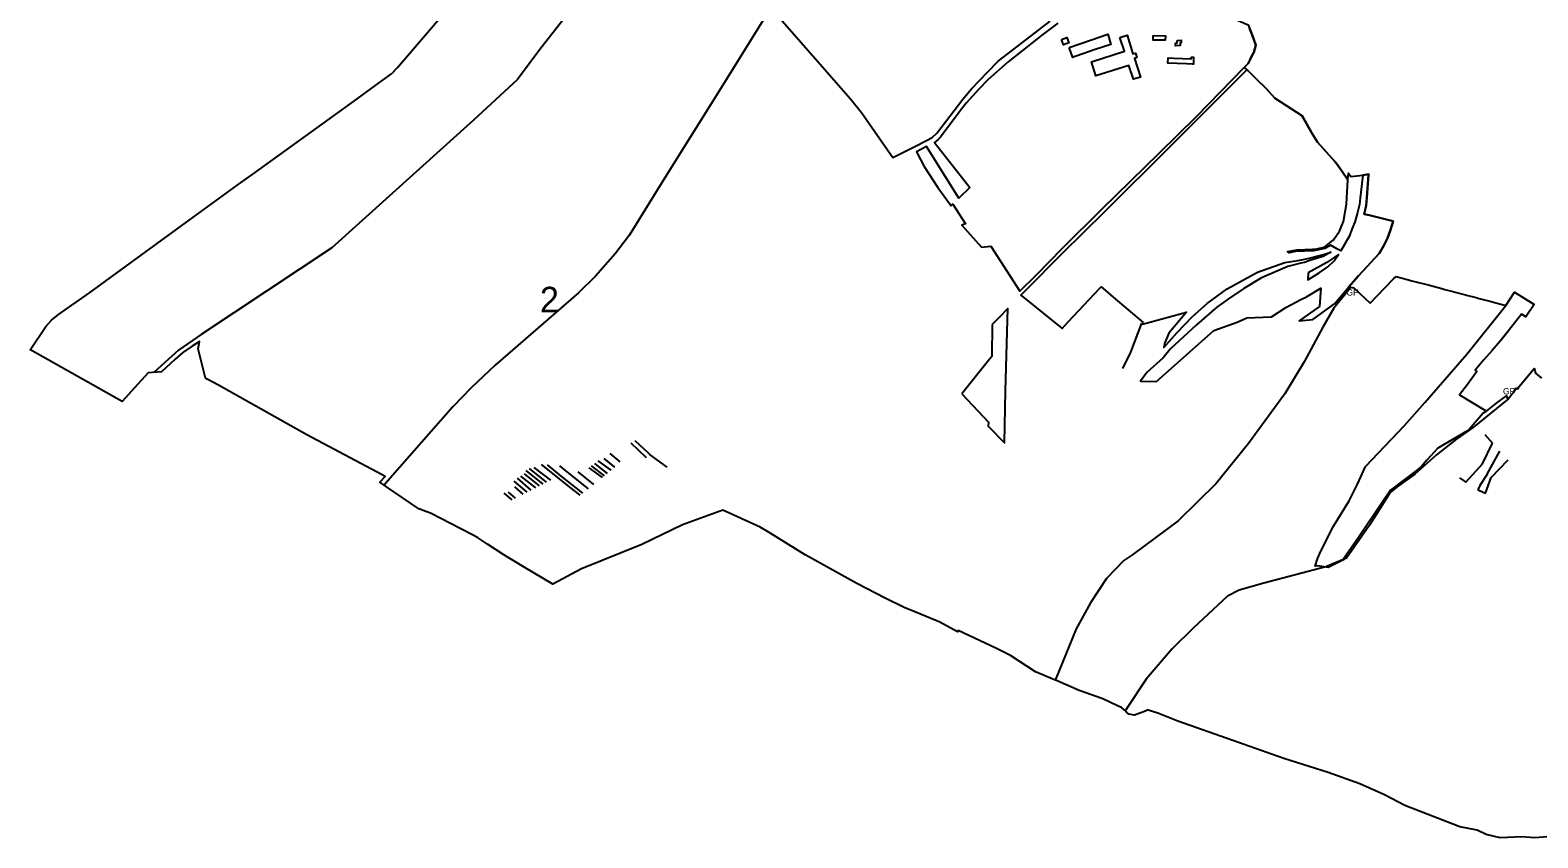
# Model space of a CAD drawing. Extents: x -584576 to -579722, y -1113169 to -1110375.
# Drawn here: x -584240 to -581887, y -1113088 to -1111827 of the extents above; entities that cross this region are included whole.
import ezdxf

# ---------------------------------------------------------------- set-up
doc = ezdxf.new("R2010")
doc.units = 0
for name, color, linetype in [('CESTY', 7, 'Continuous'), ('GRA_ZV', 7, 'Continuous'), ('LES_ZV', 7, 'Continuous'), ('Level 255', 7, 'Continuous'), ('OVNE_PRE', 7, 'Continuous'), ('OVNE_SET', 7, 'Continuous'), ('OVNI_PRE', 7, 'Continuous'), ('OVNI_SET', 7, 'Continuous'), ('VODA', 7, 'Continuous')]:
    doc.layers.add(name, color=color, linetype=linetype)

msp = doc.modelspace()

# ---------------------------------------------------------------- linework, layer by layer
at = {"layer": 'CESTY'}
for points in [[(-583086.3, -1111796.1), (-583161.2, -1111917), (-583248.8, -1112057.5), (-583304.8, -1112147.4), (-583326.6, -1112176.1), (-583357.4, -1112211.2), (-583383.9, -1112237.1), (-583513.8, -1112350.2), (-583551.3, -1112385.3), (-583579.8, -1112414.8), (-583681.5, -1112530.8), (-583687.3, -1112537.3)], [(-582178.9, -1112229.2), (-582204.8, -1112261), (-582222.1, -1112290.5), (-582251.3, -1112344.5), (-582281.6, -1112394.7), (-582338.2, -1112472.3), (-582388.4, -1112534.7), (-582447.9, -1112593.1), (-582518.9, -1112645.6), (-582532.5, -1112654.8), (-582559.9, -1112683.2), (-582584.6, -1112721.3), (-582607.2, -1112761.6), (-582639.3, -1112841)]]:
    msp.add_lwpolyline(points, dxfattribs=at)
at = {"layer": 'GRA_ZV'}
for p, q in [((-582178.6, -1112055.2), (-582178.6, -1112055.2)), ((-582112.5, -1112124.9), (-582149.6, -1112115.9)), ((-582112.5, -1112124.9), (-582112.5, -1112124.9)), ((-582210.1, -1112162.7), (-582210.1, -1112162.7)), ((-582738.4, -1112286.7), (-582738.8, -1112336.2))]:
    msp.add_line(p, q, dxfattribs=at)
for points in [[(-583076.7, -1111799.7), (-582959.4, -1111934.2), (-582942.1, -1111955.5), (-582893.2, -1112025.7), (-582874.5, -1112016.1), (-582857.8, -1112007.8), (-582840.6, -1111998.9), (-582832, -1111994.4), (-582824.5, -1111987.5), (-582784, -1111934.4), (-582770.3, -1111918.7), (-582745.7, -1111892.2), (-582728.7, -1111875.4), (-582677.4, -1111835.6), (-582647.7, -1111813)], [(-582635.5, -1111815.8), (-582660.5, -1111834.8), (-582668.5, -1111841.1), (-582713.4, -1111876.1), (-582745, -1111904.2), (-582758.9, -1111919.1), (-582778.8, -1111941.1), (-582786.6, -1111950.8), (-582818.7, -1111994.1), (-582822.2, -1111997.6), (-582828.1, -1112002.1), (-582772.9, -1112072.3), (-582790.2, -1112089.3), (-582840.8, -1112008.7), (-582856.3, -1112016.8), (-582855.2, -1112018.8), (-582844.2, -1112039.5), (-582822.9, -1112072.6), (-582803.4, -1112099.8), (-582802.6, -1112101), (-582799.8, -1112098.8), (-582779.6, -1112129.1), (-582785.5, -1112131.4), (-582755, -1112165.9), (-582740.2, -1112164.1), (-582695, -1112234.3), (-582668.7, -1112208.3), (-582629.1, -1112167.9), (-582566.3, -1112106.1), (-582477.3, -1112018.7), (-582419.3, -1111961.5), (-582344.7, -1111885.2), (-582338.8, -1111878.9), (-582335.5, -1111872.5), (-582332.3, -1111865.8), (-582330, -1111861.6), (-582326.9, -1111850.2), (-582332.6, -1111834.1), (-582336.5, -1111824)], [(-582629.8, -1111841.7), (-582621.6, -1111838.5), (-582618.5, -1111846.8), (-582626.8, -1111849.9), (-582629.8, -1111841.7)], [(-582617.8, -1111853.9), (-582583.3, -1111842.1), (-582557.7, -1111833.3), (-582557.2, -1111834.9), (-582553.9, -1111845.8), (-582552.9, -1111849), (-582577.3, -1111857.3), (-582606.9, -1111867.4), (-582609.2, -1111868.2), (-582612.5, -1111869.3), (-582614.8, -1111862.7), (-582617.8, -1111853.9)], [(-582538.7, -1111838.3), (-582527.7, -1111834.8), (-582518.4, -1111864), (-582514.5, -1111862.8), (-582514, -1111864.5), (-582512.3, -1111869.7), (-582516.1, -1111870.9), (-582506.8, -1111900.1), (-582517.8, -1111903.6), (-582524.7, -1111881.9), (-582576.3, -1111898.3), (-582583.3, -1111876.2), (-582531.8, -1111859.8), (-582538.7, -1111838.3)], [(-582486.8, -1111835.2), (-582467.7, -1111835.7), (-582468.1, -1111842.5), (-582486.8, -1111842.3), (-582486.8, -1111835.2)], [(-582449.6, -1111842.8), (-582443.2, -1111842.6), (-582443, -1111846.7), (-582445, -1111846.7), (-582444.9, -1111850.8), (-582452.2, -1111851.1), (-582452.3, -1111847), (-582449.5, -1111846.9), (-582449.6, -1111842.8)], [(-582427.4, -1111868.9), (-582423.8, -1111869), (-582424.2, -1111879.9), (-582426.3, -1111879.9), (-582434.8, -1111879.5), (-582464, -1111878.2), (-582463.7, -1111870.1), (-582454.8, -1111870.5), (-582427.5, -1111871.6), (-582427.4, -1111868.9)], [(-582340.8, -1111888.6), (-582461, -1112008.9), (-582562.8, -1112110.7), (-582628.4, -1112175.2), (-582686.5, -1112233.8), (-582693.3, -1112240.6), (-582674.9, -1112255.6), (-582629, -1112292.5), (-582619.4, -1112282.1), (-582570, -1112229.5), (-582568.2, -1112227.4), (-582557.5, -1112236.5), (-582549.1, -1112243.6), (-582502.6, -1112283.3)], [(-582324.6, -1111904.3), (-582339.1, -1111890.1), (-582340.8, -1111888.6)], [(-582199, -1112037), (-582203.4, -1112031.7), (-582230.5, -1112001.7), (-582240, -1111986.6), (-582254.3, -1111960.7), (-582297.2, -1111933), (-582310.9, -1111917.4), (-582324.6, -1111904.3)], [(-582150.6, -1112051.8), (-582159.9, -1112053.5), (-582163.8, -1112088.7), (-582164.9, -1112099.3), (-582168.2, -1112111.6), (-582172.2, -1112126.5), (-582176.8, -1112137.8), (-582180.7, -1112148.2), (-582193.8, -1112171.5), (-582198, -1112169.2), (-582200.1, -1112168.1), (-582210.1, -1112162.7), (-582218.9, -1112167.7), (-582236.6, -1112171.5), (-582264.7, -1112172.6), (-582274.6, -1112174.7), (-582277.1, -1112172.5), (-582262.1, -1112169.9), (-582238.4, -1112168.6), (-582231.7, -1112168.2), (-582220.4, -1112165.8), (-582219.7, -1112165.6), (-582205.6, -1112154.5), (-582196.1, -1112140.8), (-582190.1, -1112125.5), (-582185.4, -1112098.5), (-582183.2, -1112060.4), (-582192, -1112047.3), (-582194.4, -1112043.8), (-582199, -1112037)], [(-582149.6, -1112115.9), (-582157.4, -1112114.1), (-582154.4, -1112100.5), (-582153.5, -1112088.1), (-582150.7, -1112052.8), (-582150.6, -1112051.8)], [(-582195.2, -1112244), (-582181.4, -1112227.8), (-582166.3, -1112210.6), (-582134.3, -1112175.7), (-582127.5, -1112164.4), (-582121.4, -1112151.7), (-582117.3, -1112140.2), (-582113.3, -1112128.7), (-582112.5, -1112124.9)], [(-582449.4, -1112299.1), (-582426, -1112274.3), (-582402.9, -1112253.7), (-582371.6, -1112230.7), (-582323.9, -1112205), (-582281.5, -1112189.7), (-582261.2, -1112186.4), (-582252.6, -1112185), (-582243.5, -1112183), (-582229.2, -1112179.4), (-582221.3, -1112177.1), (-582209.4, -1112173.7), (-582221.6, -1112180.1), (-582229.1, -1112182.4), (-582243.8, -1112187.2), (-582250.6, -1112189.5), (-582256.5, -1112190.5)], [(-582245, -1112205.8), (-582245.7, -1112216.6), (-582234.4, -1112209.8), (-582228.1, -1112205.9), (-582214.3, -1112196.5), (-582204.4, -1112186.9), (-582197.6, -1112176.9), (-582216, -1112189.9), (-582245, -1112205.8)], [(-582256.5, -1112190.5), (-582276.8, -1112195.9), (-582318, -1112213.8), (-582345.4, -1112230.2), (-582369.6, -1112246.2), (-582387.7, -1112259.5), (-582419.1, -1112286.9), (-582460.3, -1112325.1), (-582471.3, -1112338.7), (-582496.8, -1112361.4), (-582506.8, -1112375), (-582481.5, -1112375.4), (-582392.4, -1112296), (-582355.8, -1112282.7), (-582340.7, -1112276.3), (-582302.2, -1112274.6)], [(-582302.2, -1112274.6), (-582279.8, -1112259.8), (-582256.3, -1112247.5), (-582247.8, -1112243.1), (-582225, -1112229.7), (-582227.5, -1112258.5), (-582259.1, -1112280.8), (-582238, -1112278.5), (-582203.7, -1112254), (-582195.2, -1112244)], [(-582205.4, -1112601.6), (-582180.8, -1112561.6), (-582167.9, -1112535.9), (-582155.8, -1112508.1), (-582094.5, -1112444.1), (-582062.8, -1112408.2), (-581997.2, -1112332.9), (-581936.5, -1112256.6), (-581922.9, -1112236.1), (-581892.3, -1112255.4), (-581905.4, -1112274.5), (-581912.3, -1112270.1), (-581929, -1112291.7), (-581945.3, -1112312.6), (-581958, -1112327), (-581971.3, -1112342.4), (-581984.5, -1112358), (-581981.6, -1112359.9)], [(-582785.6, -1112394.9), (-582743.9, -1112439.2), (-582744.4, -1112445.4), (-582718.7, -1112471.2), (-582717.2, -1112390.1), (-582713.5, -1112261.3), (-582727.8, -1112276), (-582738.4, -1112286.7)], [(-582502.6, -1112283.3), (-582503.5, -1112285.8), (-582434.7, -1112267), (-582462.6, -1112300.2), (-582469.1, -1112316.2), (-582470.1, -1112322.2), (-582449.4, -1112299.1)], [(-582738.8, -1112336.2), (-582744.1, -1112342.8), (-582785.6, -1112394.9)], [(-581981.6, -1112359.9), (-581996.6, -1112380.1), (-582009, -1112396.1)], [(-582009, -1112396.1), (-581966.8, -1112421.9), (-581971.9, -1112424.8), (-581974.9, -1112428.3)], [(-581974.9, -1112428.3), (-581994, -1112450.6), (-581997.5, -1112453.2), (-582027.7, -1112470.9), (-582042.6, -1112479.6), (-582059.6, -1112498.5)], [(-582059.6, -1112498.5), (-582068.4, -1112508.3), (-582078.3, -1112515.8), (-582116.5, -1112545), (-582166.6, -1112619.1), (-582189.4, -1112651.6), (-582188.8, -1112653.6), (-582213.9, -1112665.9)], [(-582213.9, -1112665.9), (-582226.7, -1112663.9), (-582231.6, -1112663.1), (-582234.2, -1112663.9), (-582230.7, -1112652.2), (-582225.9, -1112641.2), (-582205.4, -1112601.6)]]:
    msp.add_lwpolyline(points, dxfattribs=at)
at = {"layer": 'LES_ZV'}
for p, q in [((-581969.3, -1112458.4), (-581957.5, -1112471.8)), ((-583318.6, -1112501), (-583334.3, -1112488)), ((-583277.7, -1112494.7), (-583301.7, -1112471.7)), ((-581965.9, -1112520.1), (-581946, -1112484.3)), ((-583438.9, -1112535.7), (-583465.5, -1112514.2)), ((-583433.5, -1112532.9), (-583460.3, -1112511.2)), ((-583426.7, -1112529.5), (-583453.2, -1112509.5)), ((-583346.3, -1112525.3), (-583366.9, -1112510.2)), ((-583343.3, -1112522.9), (-583363.6, -1112507)), ((-583338.3, -1112518.9), (-583358.1, -1112503.5)), ((-583332.9, -1112514), (-583353, -1112499.1)), ((-583327.1, -1112509), (-583343.9, -1112495.6)), ((-583463.8, -1112548.3), (-583484, -1112530.9)), ((-583457.4, -1112545.1), (-583479.2, -1112526.2)), ((-583450.6, -1112541.6), (-583473.6, -1112523.3)), ((-583444.6, -1112538.6), (-583468.2, -1112519.7)), ((-583359.8, -1112536.4), (-583384.3, -1112516.4)), ((-583487.3, -1112560.2), (-583499.9, -1112549.7)), ((-583482.3, -1112557.7), (-583493.2, -1112548.1)), ((-583469.9, -1112551.4), (-583483, -1112539.7))]:
    msp.add_line(p, q, dxfattribs=at)
for points in [[(-582505.1, -1112284.4), (-582522.2, -1112329.5), (-582535, -1112355.4)], [(-583245.6, -1112509.4), (-583271.9, -1112490.1), (-583274.6, -1112487.5), (-583295.2, -1112468.2)], [(-582009, -1112526), (-581998.8, -1112532.8), (-581973.2, -1112504), (-581958.1, -1112472.8), (-581957.5, -1112471.8)], [(-583380.9, -1112552.9), (-583395.4, -1112541.8), (-583441.5, -1112505.2)], [(-583376.8, -1112549.6), (-583411.2, -1112522.7), (-583432, -1112505.8)], [(-583368.1, -1112542.8), (-583404.2, -1112514.4), (-583413, -1112507.1)], [(-581965.9, -1112520.1), (-581966.4, -1112521.1), (-581977.1, -1112537.9), (-581979.5, -1112543.6), (-581979.9, -1112544.6), (-581971.8, -1112548.2), (-581968.4, -1112549.9), (-581959.5, -1112525.4), (-581932.8, -1112497.6)]]:
    msp.add_lwpolyline(points, dxfattribs=at)
at = {"layer": 'Level 255'}
for p, q in [((-583676.8, -1112511.2), (-583676.8, -1112511.2)), ((-581960.9, -1112507.7), (-581960.9, -1112507.7))]:
    msp.add_line(p, q, dxfattribs=at)
at = {"layer": 'OVNE_PRE'}
for points in [[(-583891.8, -1112051.5), (-583740.7, -1111942.5), (-583688.5, -1111904.6), (-583675.7, -1111894.8), (-583666.2, -1111885.1), (-583600.7, -1111808.6), (-583566.2, -1111771.3), (-583537.4, -1111740.1), (-583451.5, -1111647.2), (-583441.4, -1111636.3), (-583367.8, -1111556.5), (-583325, -1111510.2), (-583316.9, -1111501.4), (-583239, -1111417.4), (-583191.9, -1111366.6), (-583170.1, -1111343.2)], [(-583966, -1112370.3), (-583977.1, -1112324.5), (-583975.1, -1112312.9), (-583986.8, -1112320.5), (-584001.1, -1112330.3), (-584013.8, -1112341.1), (-584034.7, -1112360.3), (-584055.6, -1112361.9), (-584076.8, -1112385.2), (-584095.8, -1112406.8), (-584236.3, -1112327.8), (-584239.5, -1112325.8), (-584214.8, -1112289.7), (-584206.1, -1112279.7), (-584195.4, -1112270.8), (-584147.1, -1112236.8), (-583985.5, -1112119.3), (-583911.2, -1112065.4), (-583891.8, -1112051.5)]]:
    msp.add_lwpolyline(points, dxfattribs=at)
at = {"layer": 'OVNE_SET'}
for p, q in [((-581971.3, -1112342.4), (-581971.3, -1112342.4)), ((-581958, -1112327), (-581958, -1112327)), ((-583963.2, -1112371.8), (-583966, -1112370.3))]:
    msp.add_line(p, q, dxfattribs=at)
for points in [[(-583024.4, -1112649), (-583029.8, -1112645.9), (-583086, -1112611.1), (-583100.2, -1112602.9), (-583158.5, -1112576.4), (-583221.3, -1112599.2), (-583284.8, -1112630.1), (-583379, -1112668.1), (-583423.8, -1112692.1), (-583468.6, -1112665.6), (-583500.3, -1112646.1), (-583525.9, -1112629.2), (-583541.5, -1112618.9), (-583550.4, -1112614.3), (-583614.8, -1112581.2), (-583621.8, -1112578.5), (-583633, -1112574.2), (-583634.4, -1112573.2), (-583681.8, -1112541.1), (-583694, -1112532.8), (-583685.6, -1112523.7), (-583690.4, -1112521.2), (-583807.7, -1112459), (-583945.8, -1112381.3), (-583963.2, -1112371.8)], [(-582094.2, -1113037.6), (-582125.9, -1113020.8), (-582164.5, -1113003.6), (-582213.8, -1112985.9), (-582283, -1112964.1), (-582362.5, -1112935.9), (-582448.2, -1112906), (-582479.6, -1112893.5), (-582496.5, -1112888.1), (-582497.8, -1112889.6), (-582515.8, -1112896.5), (-582525, -1112894.7), (-582528.3, -1112891.6), (-582530.7, -1112889.4), (-582532.5, -1112887.8), (-582536.3, -1112884.3), (-582542.5, -1112881.7), (-582565.5, -1112871.2), (-582602.3, -1112858), (-582636.8, -1112842.6), (-582643.7, -1112840.4), (-582670.4, -1112828.8), (-582709.8, -1112803.4), (-582732.3, -1112792.1), (-582791, -1112764.1), (-582792.1, -1112766.2), (-582819.7, -1112751.1), (-582856.3, -1112736.1), (-582875.3, -1112728.1), (-582905.4, -1112713.6), (-582949.4, -1112690.9), (-583024.4, -1112649)], [(-581859.1, -1113085.4), (-581865.3, -1113085.9), (-581866.1, -1113086), (-581867, -1113086.1), (-581878.3, -1113086.9), (-581892, -1113088.1), (-581910.8, -1113086.3), (-581945.6, -1113088), (-581967.2, -1113083), (-581981.2, -1113075.8), (-582008.4, -1113071), (-582094.2, -1113037.6)]]:
    msp.add_lwpolyline(points, dxfattribs=at)
at = {"layer": 'OVNI_PRE'}
for p, q in [((-582137.5, -1112241.9), (-582111.6, -1112215.4)), ((-582111.6, -1112215.4), (-582107.9, -1112211.6)), ((-582031.5, -1112231.7), (-582017.1, -1112235.5)), ((-581969.7, -1112247.9), (-581959.2, -1112250.7))]:
    msp.add_line(p, q, dxfattribs=at)
for points in [[(-582075.1, -1112220.2), (-582062, -1112223.6), (-582055.8, -1112225.3), (-582036.5, -1112230.4), (-582031.5, -1112231.7)], [(-581997.8, -1112240.5), (-581983.1, -1112244.4), (-581978.3, -1112245.7), (-581969.7, -1112247.9)]]:
    msp.add_lwpolyline(points, dxfattribs=at)
at = {"layer": 'OVNI_SET'}
for p, q in [((-582127.5, -1112164.4), (-582134.3, -1112175.7)), ((-582107.9, -1112211.6), (-582099.7, -1112213.8)), ((-582099.7, -1112213.8), (-582090.6, -1112216.2)), ((-582090.6, -1112216.2), (-582081, -1112218.7)), ((-582081, -1112218.7), (-582076.7, -1112219.8)), ((-582076.7, -1112219.8), (-582075.1, -1112220.2)), ((-582148.5, -1112253.1), (-582137.5, -1112241.9)), ((-581999.4, -1112240.1), (-581997.8, -1112240.5)), ((-581959.2, -1112250.7), (-581952.2, -1112252.5)), ((-581927, -1112395.5), (-581924.8, -1112392.7))]:
    msp.add_line(p, q, dxfattribs=at)
for points in [[(-582369.8, -1111805.2), (-582338.7, -1111818.5), (-582336.5, -1111824), (-582332.6, -1111834.1)], [(-582332.6, -1111834.1), (-582326.9, -1111850.2), (-582330, -1111861.6), (-582332.3, -1111865.8), (-582335.5, -1111872.5), (-582338.8, -1111878.9)], [(-582338.8, -1111878.9), (-582344.7, -1111885.2), (-582340.8, -1111888.6), (-582339.1, -1111890.1), (-582324.6, -1111904.3), (-582310.9, -1111917.4)], [(-582310.9, -1111917.4), (-582297.2, -1111933), (-582254.3, -1111960.7), (-582240, -1111986.6), (-582230.5, -1112001.7)], [(-582230.5, -1112001.7), (-582203.4, -1112031.7), (-582199, -1112037), (-582194.4, -1112043.8), (-582192, -1112047.3)], [(-582192, -1112047.3), (-582183.2, -1112060.4), (-582182.2, -1112050.1), (-582178.6, -1112055.2), (-582159.9, -1112053.5)], [(-582159.9, -1112053.5), (-582150.6, -1112051.8), (-582150.7, -1112052.8), (-582153.5, -1112088.1), (-582154.4, -1112100.5), (-582157.4, -1112114.1), (-582152.3, -1112115.3), (-582149.6, -1112115.9)], [(-582149.6, -1112115.9), (-582112.5, -1112124.9), (-582113.3, -1112128.7), (-582117.3, -1112140.2), (-582121.4, -1112151.7), (-582127.5, -1112164.4)], [(-582134.3, -1112175.7), (-582166.3, -1112210.6), (-582181.4, -1112227.8)], [(-582181.4, -1112227.8), (-582173.9, -1112229.2), (-582172.8, -1112230.3), (-582148.5, -1112253.1)], [(-582017.1, -1112235.5), (-582015.8, -1112235.8), (-581999.4, -1112240.1)], [(-581952.2, -1112252.5), (-581936.5, -1112256.6), (-581922.9, -1112236.1)], [(-581922.9, -1112236.1), (-581918.7, -1112238.8), (-581897.1, -1112252.3), (-581894.6, -1112253.9)], [(-581894.6, -1112253.9), (-581892.3, -1112255.4), (-581905.4, -1112274.5), (-581908.6, -1112272.5), (-581911, -1112270.9)], [(-581911, -1112270.9), (-581912.3, -1112270.1), (-581929, -1112291.7), (-581944, -1112311), (-581945.3, -1112312.6)], [(-581945.3, -1112312.6), (-581958, -1112327), (-581971.3, -1112342.4)], [(-581971.3, -1112342.4), (-581984.5, -1112358), (-581981.6, -1112359.9), (-581996.6, -1112380.1)], [(-581916.4, -1112383.9), (-581892.2, -1112355.4), (-581891.5, -1112357.7), (-581890.2, -1112362.2), (-581880.9, -1112370.3)], [(-581996.6, -1112380.1), (-582009, -1112396.1), (-581966.8, -1112421.9), (-581951.3, -1112409.5), (-581947, -1112406.4)], [(-581933.9, -1112402.7), (-581933.3, -1112403.6), (-581927, -1112395.5)], [(-581924.8, -1112392.7), (-581920.6, -1112385.8), (-581917.3, -1112386.7), (-581916.4, -1112383.9)], [(-581947, -1112406.4), (-581935.5, -1112398.1), (-581933.9, -1112402.7)]]:
    msp.add_lwpolyline(points, dxfattribs=at)
at = {"layer": 'VODA'}
for points in [[(-583166.3, -1111332.7), (-583144.8, -1111416.2), (-583164.1, -1111492.3), (-583211.4, -1111560.2), (-583442.7, -1111855), (-583478.9, -1111903.8), (-583547.6, -1111967.3), (-583768.6, -1112166.8), (-583972.6, -1112302), (-584008.1, -1112326.4), (-584045.8, -1112361.1)], [(-581934.3, -1112404.1), (-581987.1, -1112446.6), (-582013, -1112465.1), (-582044.8, -1112489.8), (-582078.4, -1112520.1), (-582104.2, -1112538.2), (-582116.8, -1112549), (-582149.3, -1112599.9), (-582185.2, -1112651.3), (-582217.3, -1112664.6), (-582265, -1112677.1), (-582314.1, -1112690.4), (-582352.6, -1112701.5), (-582370.7, -1112710.4), (-582423.9, -1112759.9), (-582457.1, -1112793.1), (-582497.8, -1112840.4), (-582529.6, -1112888.1)]]:
    msp.add_lwpolyline(points, dxfattribs=at)

# ---------------------------------------------------------------- texts
at = {"layer": 'Level 255'}
for s, height, p in [('2', 40, (-583444, -1112267.6)), ('GP', 10, (-582185.3, -1112241.3)), ('GP', 10, (-581941, -1112395.7))]:
    msp.add_text(s, height=height, dxfattribs=at).set_placement(p)

doc.saveas('drawing.dxf')
